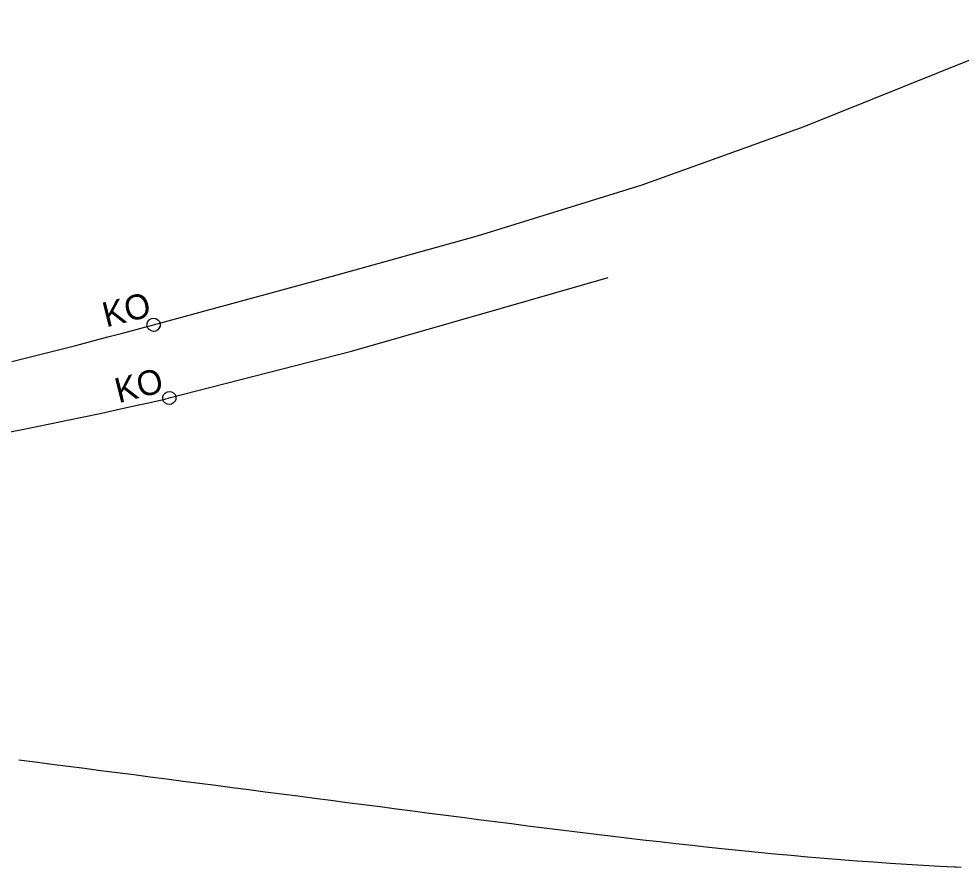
# Model space of a CAD drawing. Extents: x -669661 to -669105, y -977202 to -977030.
# Drawn here: x -669168.055 to -669165.209, y -977098.791 to -977096.23 of the extents above; entities that cross this region are included whole.
import ezdxf

# ---------------------------------------------------------------- set-up
doc = ezdxf.new("R2010")
doc.units = 0
doc.layers.add('Schéma', color=7, linetype='Continuous')

msp = doc.modelspace()

# ---------------------------------------------------------------- linework, layer by layer
at = {"layer": 'Schéma'}
for p, q in [((-669167.7372, -977097.1773), (-669167.6889, -977097.1644)), ((-669167.6889, -977097.1644), (-669167.6477, -977097.1533)), ((-669167.8339, -977097.2028), (-669167.7856, -977097.1901)), ((-669167.7856, -977097.1901), (-669167.7372, -977097.1773)), ((-669167.9792, -977097.2402), (-669167.9308, -977097.2279)), ((-669167.9308, -977097.2279), (-669167.8823, -977097.2154)), ((-669167.8823, -977097.2154), (-669167.8339, -977097.2028)), ((-669168.0762, -977097.2646), (-669168.0277, -977097.2524)), ((-669168.0277, -977097.2524), (-669167.9792, -977097.2402)), ((-669167.7605, -977097.4103), (-669167.7117, -977097.3995)), ((-669167.7117, -977097.3995), (-669167.6629, -977097.3886)), ((-669167.6629, -977097.3886), (-669167.6141, -977097.3775)), ((-669167.6141, -977097.3775), (-669167.6002, -977097.3743)), ((-669167.8583, -977097.4312), (-669167.8094, -977097.4208)), ((-669167.8094, -977097.4208), (-669167.7605, -977097.4103)), ((-669168.0052, -977097.4613), (-669167.9562, -977097.4515)), ((-669167.9562, -977097.4515), (-669167.9072, -977097.4415)), ((-669167.9072, -977097.4415), (-669167.8583, -977097.4312)), ((-669168.1034, -977097.4805), (-669168.0543, -977097.471)), ((-669168.0543, -977097.471), (-669168.0052, -977097.4613))]:
    msp.add_line(p, q, dxfattribs=at)
for points in [[(-669167.6477, -977097.1533), (-669167.6477, -977097.1533), (-669167.1113, -977097.0073), (-669166.6696, -977096.8845), (-669166.1728, -977096.7303), (-669165.6832, -977096.5547), (-669165.185, -977096.3539), (-669164.9013, -977096.2295)], [(-669167.6002, -977097.3743), (-669167.6002, -977097.3743), (-669167.0504, -977097.2329), (-669166.5967, -977097.1032), (-669166.2755, -977097.011)], [(-669167.6481, -977097.1733), (-669167.6547, -977097.1719), (-669167.6613, -977097.1677), (-669167.6652, -977097.1637), (-669167.6678, -977097.157), (-669167.6676, -977097.149), (-669167.6649, -977097.1437), (-669167.6608, -977097.1384), (-669167.654, -977097.1345), (-669167.6474, -977097.1333), (-669167.6407, -977097.1348), (-669167.6341, -977097.1389), (-669167.6302, -977097.143), (-669167.6277, -977097.1497), (-669167.6278, -977097.1577), (-669167.6306, -977097.163), (-669167.6347, -977097.1682), (-669167.6414, -977097.1721), (-669167.6481, -977097.1733)], [(-669167.6481, -977097.1733), (-669167.6547, -977097.1719), (-669167.6613, -977097.1677), (-669167.6652, -977097.1637), (-669167.6678, -977097.157), (-669167.6676, -977097.149), (-669167.6649, -977097.1437), (-669167.6608, -977097.1384), (-669167.654, -977097.1345), (-669167.6474, -977097.1333), (-669167.6407, -977097.1348), (-669167.6341, -977097.1389), (-669167.6302, -977097.143), (-669167.6277, -977097.1497), (-669167.6278, -977097.1577), (-669167.6306, -977097.163), (-669167.6347, -977097.1682), (-669167.6414, -977097.1721), (-669167.6481, -977097.1733)], [(-669167.6006, -977097.3943), (-669167.6072, -977097.3928), (-669167.6138, -977097.3887), (-669167.6177, -977097.3846), (-669167.6203, -977097.3779), (-669167.6201, -977097.3699), (-669167.6173, -977097.3646), (-669167.6132, -977097.3594), (-669167.6065, -977097.3555), (-669167.5998, -977097.3543), (-669167.5932, -977097.3557), (-669167.5866, -977097.3598), (-669167.5827, -977097.3639), (-669167.5801, -977097.3706), (-669167.5803, -977097.3786), (-669167.583, -977097.3839), (-669167.5871, -977097.3892), (-669167.5939, -977097.3931), (-669167.6006, -977097.3943)], [(-669168.0546, -977098.4667), (-669168.005, -977098.4731), (-669167.9555, -977098.4796), (-669167.9059, -977098.486), (-669167.8563, -977098.4924), (-669167.8067, -977098.4989), (-669167.7571, -977098.5053), (-669167.7075, -977098.5117), (-669167.6579, -977098.5182), (-669167.6084, -977098.5246), (-669167.5588, -977098.5311), (-669167.5092, -977098.5375), (-669167.4596, -977098.5439), (-669167.41, -977098.5504), (-669167.3604, -977098.5568), (-669167.3109, -977098.5633), (-669167.2613, -977098.5697), (-669167.2117, -977098.5761), (-669167.1621, -977098.5826), (-669167.1125, -977098.589), (-669167.0629, -977098.5954), (-669167.0134, -977098.6019), (-669166.9638, -977098.6083), (-669166.9142, -977098.6148), (-669166.8646, -977098.6212), (-669166.8297, -977098.6257), (-669166.815, -977098.6276), (-669166.7654, -977098.6341), (-669166.7166, -977098.6404), (-669166.7159, -977098.6405), (-669166.6663, -977098.6469), (-669166.6167, -977098.6533), (-669166.5671, -977098.6596), (-669166.5175, -977098.6659), (-669166.4679, -977098.6722), (-669166.4183, -977098.6784), (-669166.3686, -977098.6845), (-669166.319, -977098.6906), (-669166.2694, -977098.6966), (-669166.2197, -977098.7025), (-669166.1701, -977098.7083), (-669166.1204, -977098.714), (-669166.0707, -977098.7196), (-669166.021, -977098.7251), (-669165.9713, -977098.7304), (-669165.9216, -977098.7357), (-669165.8718, -977098.7407), (-669165.8221, -977098.7457), (-669165.7723, -977098.7504), (-669165.7225, -977098.755), (-669165.6727, -977098.7595), (-669165.6229, -977098.7637), (-669165.573, -977098.7678), (-669165.5232, -977098.7717), (-669165.4733, -977098.7753), (-669165.4234, -977098.7788), (-669165.3736, -977098.782), (-669165.3236, -977098.785), (-669165.2737, -977098.7878), (-669165.2287, -977098.7901), (-669165.2238, -977098.7903), (-669165.2091, -977098.791)]]:
    msp.add_lwpolyline(points, dxfattribs=at)

# ---------------------------------------------------------------- texts
for p in [(-669167.7911, -977097.1613), (-669167.7537, -977097.39)]:
    msp.add_text('KO', height=0.075, rotation=13.9741, dxfattribs=at).set_placement(p)

doc.saveas('drawing.dxf')
